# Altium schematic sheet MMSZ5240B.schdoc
size 127 x 101 mm
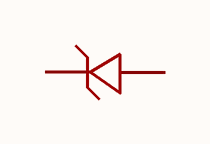
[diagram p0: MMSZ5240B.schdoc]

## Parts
ZD?  mmsz5240b_c21564  [SOD-123_L2.8-W1.8-LS3.7-RD]  (value not drawn)

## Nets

Not connected (* = marked no-connect by the designer): ZD? 1(K) 2(A)

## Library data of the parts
ZD? = mmsz5240b_c21564: 二极管配置:1个独立式;稳压值(标称值):10V;稳压值(范围):9.5V~10.5V;耗散功率(Pd):350mW;; Manufacturer: CJ(江苏长电/长晶); AddInBom: yes; ModelId: 7884390a25fb4c08947731ebfba7e3f8; ModelTransform: 144.8816,62.992,0,0,0,0,0,0,0; Diode Configuration: 1个独立式; Zener Voltage(Nom): 10V; Reverse Leakage Current (Ir): 3uA; Pd - Power Dissipation: 350mW; Impedance(Zzt): 17Ω; Impedance(Zzk): 600Ω; Operating Junction Temperature Range: -65℃~+150℃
